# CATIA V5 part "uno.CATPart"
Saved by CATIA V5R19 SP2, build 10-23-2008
Part number: uno
Revision: ANY
Definition: UNKNOWN
Nomenclature: uno
Source: Unknown
Bounding box of the stored display mesh (mm): x -7 to 68, y 0 to 12.6, z -53 to 0
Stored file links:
  Z:\fausse table rondelle-20220905T211342Z-001\fausse table rondelle\uno.CATPart
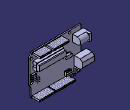
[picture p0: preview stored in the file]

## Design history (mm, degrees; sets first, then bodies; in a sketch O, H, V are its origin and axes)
AxisSystem1: origin (0, 0, 0), X (1, 0, 0), Y (0, 1, 0), Z (0, 0, 1)
Body1 "Chamfer1" (main body)
  Solid1: solid without history
Body2 "Fillet1"
  Solid2: solid without history
Body3 "Boss-Extrude4[1]"
  Solid3: solid without history
Body4 "Boss-Extrude4[2]"
  Solid4: solid without history
Body5 "Boss-Extrude4[3]"
  Solid5: solid without history
Body6 "Boss-Extrude4[4]"
  Solid6: solid without history
Body7 "Cut-Extrude4"
  Solid7: solid without history
Body8 "Chamfer2"
  Solid8: solid without history
Body9 "Boss-Extrude12"
  Solid9: solid without history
